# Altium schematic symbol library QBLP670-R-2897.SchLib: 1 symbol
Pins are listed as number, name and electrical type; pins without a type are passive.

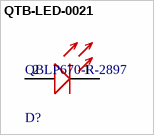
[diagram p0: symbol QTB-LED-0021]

## QTB-LED-0021
designator D?, comment QBLP670-R-2897
LED RED CLEAR 2PLCC SMD; Manufacturer: QT Brightek (QTB); Luminous Intensity: 690mcd; Test Current: 20mA; Lens Color: Colorless; Lens Style: Oval with Flat Top; Forward Voltage: 2.0V; Wavelength - Dominant: 620nm; Viewing Angle: 120°
footprint QBLP670-R-2897 (Footprint not found)
pins: 1 ANODE (+), 2 CATHODE (-)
